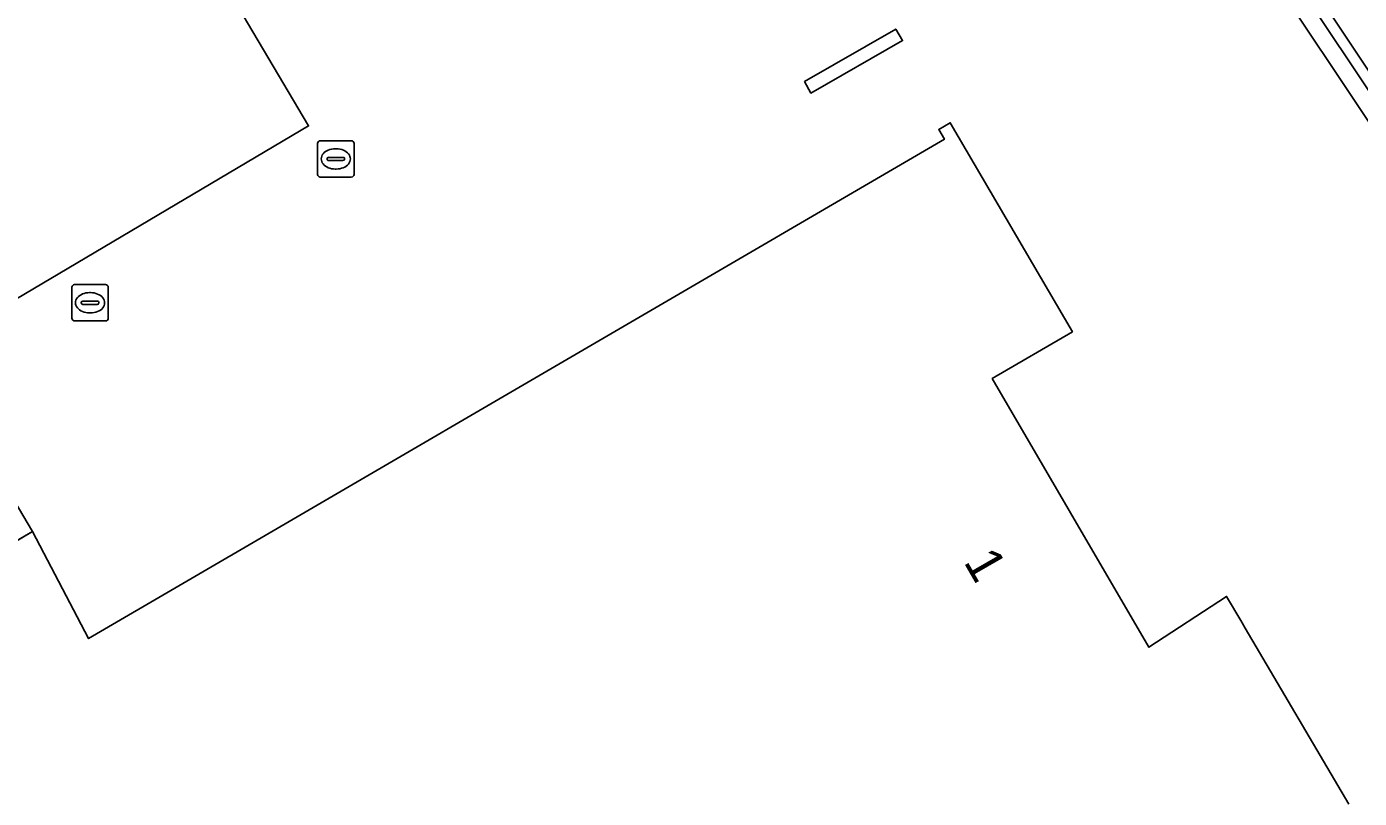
# Model space of a CAD drawing. Extents: x 158352 to 159489, y 383828 to 384603.
# Drawn here: x 158691.58 to 158728.21, y 384163.88 to 384185.09 of the extents above; entities that cross this region are included whole.
import ezdxf

# ---------------------------------------------------------------- set-up
doc = ezdxf.new("R2010")
doc.units = 0
for name, color, linetype in [('IMGEO_Erf', 7, 'Continuous'), ('IMGEO_Groenvoorziening', 7, 'Continuous'), ('IMGEO_Hek', 7, 'Continuous'), ('IMGEO_Kolk', 7, 'Continuous'), ('IMGEO_Pand', 7, 'Continuous'), ('IMGEO_Pand_nummerreeks', 7, 'Continuous'), ('IMGEO_Pand_vergunning_verleend', 7, 'Continuous'), ('IMGEO_Voetpad_open', 7, 'Continuous')]:
    doc.layers.add(name, color=color, linetype=linetype)

msp = doc.modelspace()

# ---------------------------------------------------------------- linework, layer by layer
at = {"layer": 'IMGEO_Erf'}
for points in [[(158732.078, 384163.004), (158734.56, 384164.453), (158730.926, 384170.674), (158730.313, 384171.723), (158730.24, 384171.849), (158734.136, 384174.169), (158730.72, 384179.098), (158723.614, 384189.764), (158724.023, 384190.002), (158700.665, 384224.966)], [(158681.775, 384165.414), (158691.734, 384171.213), (158693.277, 384168.267), (158698.464, 384171.293), (158716.807, 384181.994), (158716.653, 384182.267), (158716.968, 384182.45), (158720.325, 384176.703), (158718.123, 384175.417), (158722.428, 384168.028), (158724.563, 384169.427), (158724.981, 384168.716), (158724.989, 384168.703), (158725.073, 384168.559), (158727.921, 384163.713)]]:
    msp.add_lwpolyline(points, dxfattribs=at)
msp.add_lwpolyline([(158712.964, 384183.581), (158715.467, 384185.026), (158715.656, 384184.709), (158713.139, 384183.266)], close=True, dxfattribs=at)
at = {"layer": 'IMGEO_Groenvoorziening'}
for points in [[(158734.468, 384174.367), (158740.785, 384164.877), (158709.334, 384146.504), (158709.408, 384146.369), (158741.091, 384164.958), (158724.283, 384190.153), (158724.023, 384190.002)], [(158724.023, 384190.002), (158723.614, 384189.764), (158730.72, 384179.098), (158734.136, 384174.169), (158734.468, 384174.367)]]:
    msp.add_lwpolyline(points, close=True, dxfattribs=at)
at = {"layer": 'IMGEO_Hek'}
msp.add_lwpolyline([(158734.468, 384174.367), (158724.023, 384190.002)], dxfattribs=at)
at = {"layer": 'IMGEO_Kolk'}
for p, q in [((158699.649, 384181.956), (158700.501, 384181.956)), ((158699.574, 384181.03), (158699.574, 384181.882)), ((158700.062, 384181.736), (158700.087, 384181.736)), ((158700.575, 384181.882), (158700.575, 384181.03)), ((158699.833, 384181.45), (158699.833, 384181.462)), ((158700.271, 384181.413), (158699.873, 384181.413)), ((158699.876, 384181.499), (158700.274, 384181.499)), ((158700.317, 384181.462), (158700.317, 384181.45)), ((158700.501, 384180.956), (158699.649, 384180.956)), ((158700.085, 384181.176), (158700.06, 384181.176)), ((158692.818, 384177.074), (158692.818, 384177.926)), ((158692.893, 384178), (158693.745, 384178)), ((158693.819, 384177.926), (158693.819, 384177.074)), ((158693.306, 384177.78), (158693.331, 384177.78)), ((158693.077, 384177.494), (158693.077, 384177.506)), ((158693.515, 384177.457), (158693.117, 384177.457)), ((158693.12, 384177.543), (158693.518, 384177.543)), ((158693.329, 384177.22), (158693.304, 384177.22)), ((158693.561, 384177.506), (158693.561, 384177.494)), ((158693.745, 384177), (158692.893, 384177))]:
    msp.add_line(p, q, dxfattribs=at)
for points in [[(158699.649, 384181.956), (158700.501, 384181.956)], [(158699.574, 384181.03), (158699.574, 384181.882)], [(158700.575, 384181.882), (158700.575, 384181.03)], [(158700.501, 384180.956), (158699.649, 384180.956)], [(158692.818, 384177.074), (158692.818, 384177.926)], [(158692.893, 384178), (158693.745, 384178)], [(158693.819, 384177.926), (158693.819, 384177.074)], [(158693.745, 384177), (158692.893, 384177)]]:
    msp.add_lwpolyline(points, dxfattribs=at)
for centre, radius, start, end in [((158699.651, 384181.88), 0.0765, 91.552, 178.448), ((158699.651, 384181.88), 0.0765, 91.552, 178.448), ((158700.499, 384181.88), 0.0765, 1.552, 88.448), ((158700.499, 384181.88), 0.0765, 1.552, 88.448), ((158699.873, 384181.459), 0.0403, 85.8775, 175.7526), ((158699.87, 384181.449), 0.0366, 178.938, 274.7102), ((158700.274, 384181.456), 0.043, 264.8664, 352.4533), ((158700.278, 384181.461), 0.0386, 1.7309, 96.639), ((158699.651, 384181.032), 0.0765, 181.552, 268.448), ((158699.651, 384181.032), 0.0765, 181.552, 268.448), ((158700.499, 384181.032), 0.0765, 271.552, 358.448), ((158700.499, 384181.032), 0.0765, 271.552, 358.448), ((158692.895, 384177.924), 0.0765, 91.552, 178.448), ((158692.895, 384177.924), 0.0765, 91.552, 178.448), ((158693.743, 384177.924), 0.0765, 1.552, 88.448), ((158693.743, 384177.924), 0.0765, 1.552, 88.448), ((158693.117, 384177.503), 0.0403, 85.8775, 175.7526), ((158693.114, 384177.493), 0.0366, 178.938, 274.7102), ((158693.518, 384177.5), 0.043, 264.8664, 352.4533), ((158693.522, 384177.505), 0.0386, 1.7309, 96.639), ((158692.895, 384177.076), 0.0765, 181.552, 268.448), ((158692.895, 384177.076), 0.0765, 181.552, 268.448), ((158693.743, 384177.076), 0.0765, 271.552, 358.448), ((158693.743, 384177.076), 0.0765, 271.552, 358.448)]:
    msp.add_arc(centre, radius, start, end, dxfattribs=at)
for centre, major_axis, ratio, start_param, end_param in [((158700.061, 384181.456), (-0.387, 0.002), 0.722429, 4.712389, 7.853982), ((158700.086, 384181.456), (-0.39, 0.002), 0.717154, 1.570796, 4.712389), ((158693.305, 384177.5), (-0.387, 0.002), 0.722429, 4.712389, 7.853982), ((158693.33, 384177.5), (-0.39, 0.002), 0.717154, 1.570796, 4.712389)]:
    msp.add_ellipse(centre, major_axis=major_axis, ratio=ratio, start_param=start_param, end_param=end_param, dxfattribs=at)
at = {"layer": 'IMGEO_Pand'}
msp.add_lwpolyline([(158715.656, 384184.709), (158715.467, 384185.026), (158712.964, 384183.581), (158713.139, 384183.266)], close=True, dxfattribs=at)
msp.add_lwpolyline([(158727.921, 384163.713), (158725.073, 384168.559), (158724.989, 384168.703), (158724.981, 384168.716), (158724.563, 384169.427), (158722.428, 384168.028), (158718.123, 384175.417), (158720.325, 384176.703), (158716.968, 384182.45), (158716.653, 384182.267), (158716.807, 384181.994), (158698.464, 384171.293), (158693.277, 384168.267), (158691.734, 384171.213), (158681.775, 384165.414), (158681.631, 384165.33), (158681.045, 384164.988), (158653.807, 384149.125)], dxfattribs=at)
at = {"layer": 'IMGEO_Pand_vergunning_verleend'}
msp.add_lwpolyline([(158663.73, 384199.45), (158670.25, 384203.312), (158671.756, 384200.771), (158684.094, 384208.079), (158699.326, 384182.365), (158688.816, 384176.139), (158691.734, 384171.213), (158689.137, 384169.675), (158686.219, 384174.601), (158680.468, 384171.194)], close=True, dxfattribs=at)
at = {"layer": 'IMGEO_Voetpad_open'}
msp.add_lwpolyline([(158690.826, 384240.042), (158724.283, 384190.153), (158741.091, 384164.958), (158743.744, 384163.971)], dxfattribs=at)

# ---------------------------------------------------------------- texts
at = {"layer": 'IMGEO_Pand_nummerreeks'}
msp.add_text('1', height=1, rotation=299.9139, dxfattribs=at).set_placement((158717.322, 384170.381))

doc.saveas('drawing.dxf')
